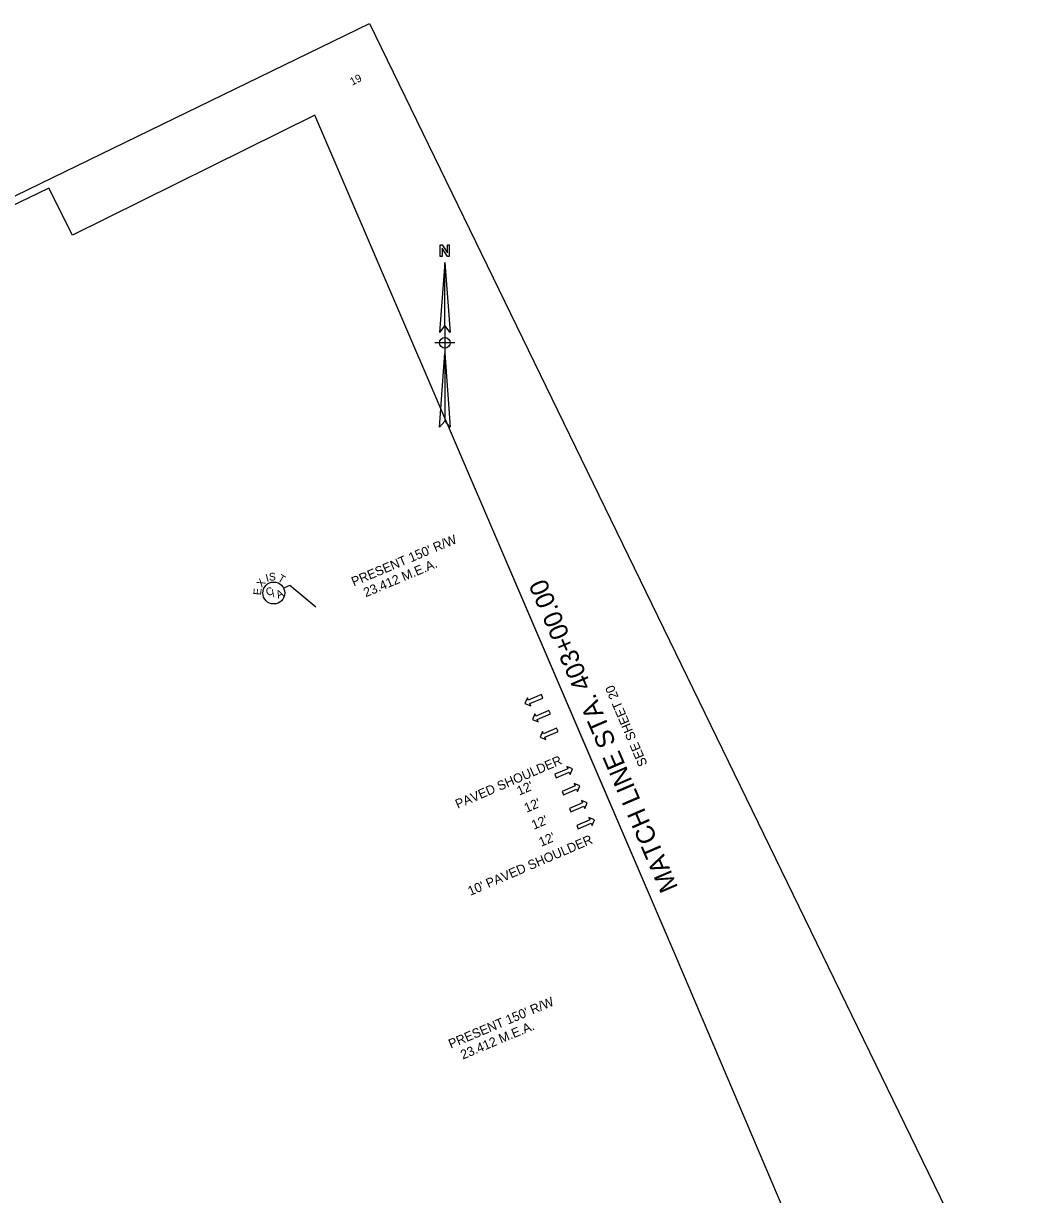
# Model space of a CAD drawing. Extents: x 1616869 to 1620470, y 1100482 to 1103335.
# Drawn here: x 1618151 to 1618793, y 1101340 to 1102097 of the extents above; entities that cross this region are included whole.
import ezdxf

# ---------------------------------------------------------------- set-up
doc = ezdxf.new("R2010")
doc.units = 0
for name, color, linetype in [('Level 2', 7, 'Continuous'), ('Level 4', 7, 'Continuous'), ('RD_PD_DR_Pipe', 7, 'Continuous'), ('RD_SHT_MatchLine', 7, 'Continuous'), ('RD_SHT_Misc2', 7, 'Continuous'), ('RD_SHT_TX', 7, 'Continuous'), ('RD_TX_RoadID', 7, 'Continuous'), ('RD_TX_RW', 7, 'Continuous')]:
    doc.layers.add(name, color=color, linetype=linetype)

msp = doc.modelspace()

# ---------------------------------------------------------------- linework, layer by layer
at = {"layer": 'Level 2'}
msp.add_lwpolyline([(1616868.78, 1101364.63), (1618375.15, 1102097.07), (1618793.41, 1101236.86), (1617287.04, 1100504.42)], close=True, dxfattribs=at)
at = {"layer": 'Level 4'}
msp.add_lwpolyline([(1617080.14, 1101099.03), (1617256.2, 1100856.12), (1617395.1, 1100558.35), (1618700.82, 1101193.66), (1618573.12, 1101494.1), (1618454.8, 1101769.78), (1618339.83, 1102037.66), (1618182.95, 1101960.1), (1618167.86, 1101990.6), (1616961.35, 1101407.95), (1616972.59, 1101384.68), (1616914.03, 1101356.41)], close=True, dxfattribs=at)
msp.add_lwpolyline([(1617080.14, 1101099.03), (1617256.2, 1100856.12), (1617395.1, 1100558.35), (1618700.82, 1101193.66), (1618573.12, 1101494.1), (1618454.8, 1101769.78), (1618339.83, 1102037.66), (1618182.95, 1101960.1), (1618167.86, 1101990.6), (1616961.35, 1101407.95), (1616972.59, 1101384.68), (1616914.03, 1101356.41)], close=True, dxfattribs=at)
at = {"layer": 'RD_PD_DR_Pipe'}
for p, q in [((1618319.54, 1101731.95), (1618323.66, 1101733.95)), ((1618323.66, 1101733.95), (1618340.43, 1101719.93))]:
    msp.add_line(p, q, dxfattribs=at)
msp.add_circle((1618313.17, 1101728.85), 7.08, dxfattribs=at)
at = {"layer": 'RD_SHT_MatchLine'}
msp.add_lwpolyline([(1618573.12, 1101494.1), (1618513.96, 1101631.94), (1618454.8, 1101769.78)], dxfattribs=at)
at = {"layer": 'RD_SHT_Misc2'}
for points in [[(1618487.13, 1101660.94), (1618486.19, 1101663.15), (1618477.74, 1101659.59), (1618477.11, 1101661.09), (1618475.6, 1101657.39), (1618479.31, 1101655.88), (1618478.67, 1101657.38)], [(1618491.98, 1101650.65), (1618491.05, 1101652.86), (1618482.6, 1101649.3), (1618481.97, 1101650.8), (1618480.46, 1101647.09), (1618484.16, 1101645.59), (1618483.53, 1101647.09)], [(1618496.94, 1101639.21), (1618496.01, 1101641.42), (1618487.56, 1101637.86), (1618486.92, 1101639.36), (1618485.41, 1101635.66), (1618489.12, 1101634.15), (1618488.49, 1101635.65)], [(1618494.85, 1101611.63), (1618495.8, 1101609.43), (1618504.23, 1101613.05), (1618504.87, 1101611.55), (1618506.35, 1101615.27), (1618502.64, 1101616.75), (1618503.28, 1101615.25)], [(1618499.59, 1101600.61), (1618500.53, 1101598.4), (1618508.96, 1101602.02), (1618509.61, 1101600.52), (1618511.09, 1101604.24), (1618507.37, 1101605.72), (1618508.02, 1101604.23)], [(1618504.32, 1101589.58), (1618505.27, 1101587.38), (1618513.7, 1101590.99), (1618514.34, 1101589.5), (1618515.82, 1101593.21), (1618512.11, 1101594.7), (1618512.75, 1101593.2)], [(1618509.06, 1101578.55), (1618510, 1101576.35), (1618518.43, 1101579.97), (1618519.07, 1101578.47), (1618520.56, 1101582.19), (1618516.84, 1101583.67), (1618517.48, 1101582.17)]]:
    msp.add_lwpolyline(points, close=True, dxfattribs=at)
at = {"layer": 'RD_SHT_TX'}
msp.add_line((1618496.66, 1101624.14), (1618496.66, 1101624.14), dxfattribs=at)
at = {"layer": 'RD_TX_RoadID'}
for p, q in [((1618423.74, 1101942.49), (1618420.32, 1101897.17)), ((1618423.74, 1101901.82), (1618420.32, 1101897.17)), ((1618423.74, 1101901.82), (1618423.74, 1101883.98)), ((1618430.26, 1101890.6), (1618417.28, 1101890.6)), ((1618423.74, 1101883.98), (1618427.15, 1101836.14)), ((1618427.15, 1101836.14), (1618423.74, 1101839.97))]:
    msp.add_line(p, q, dxfattribs=at)
msp.add_lwpolyline([(1618426.67, 1101946.31), (1618425.44, 1101946.31), (1618422.03, 1101951.78), (1618422.03, 1101950.96), (1618422.03, 1101946.31), (1618420.8, 1101946.31), (1618420.8, 1101953.9), (1618422.03, 1101953.9), (1618425.44, 1101948.84), (1618425.44, 1101949.25), (1618425.44, 1101953.9), (1618426.67, 1101953.9), (1618426.67, 1101946.31)], dxfattribs=at)
for points in [[(1618423.74, 1101942.49), (1618427.15, 1101897.17), (1618423.74, 1101901.82)], [(1618423.74, 1101883.98), (1618423.74, 1101839.97), (1618420.32, 1101836.14)]]:
    msp.add_lwpolyline(points, close=True, dxfattribs=at)
msp.add_circle((1618423.77, 1101890.6), 3.45, dxfattribs=at)

# ---------------------------------------------------------------- texts
at = {"layer": 'RD_PD_DR_Pipe'}
for s, rotation, p in [('X', 51.02398, (1618305.4, 1101732.09)), ('I', 15.86251, (1618308.69, 1101735.98)), ('S', 4.14202, (1618310.23, 1101736.74)), ('T', 328.98055, (1618315.31, 1101736.99)), ('E', 84.5111, (1618304.9, 1101727.27)), ('C', 25.92721, (1618309.43, 1101726.59)), ('/', 25.92721, (1618313.01, 1101725.99)), ('A', 25.92721, (1618316.05, 1101725.08))]:
    msp.add_text(s, height=5, rotation=rotation, dxfattribs=at).set_placement(p)
at = {"layer": 'RD_SHT_MatchLine'}
for s, height, p in [('MATCH LINE STA. 403+00.00', 12, (1618574.75, 1101538.46)), ('SEE SHEET 20', 6, (1618554.89, 1101618.23))]:
    msp.add_text(s, height=height, rotation=113.22835, dxfattribs=at).set_placement(p)
at = {"layer": 'RD_SHT_TX'}
for s, height, rotation, p in [('19', 5, 25.93046, (1618363.88, 1102056.84)), (' PAVED SHOULDER', 6, 23.23628, (1618430.05, 1101588.42)), ("12'", 6, 23.23465, (1618471.88, 1101597.81)), ("12'", 6, 23.23465, (1618476.61, 1101586.78)), ("12'", 6, 23.23465, (1618481.35, 1101575.76)), ("10' PAVED SHOULDER", 6, 23.23628, (1618440.24, 1101533.05)), ("12'", 6, 23.23465, (1618486.08, 1101564.73))]:
    msp.add_text(s, height=height, rotation=rotation, dxfattribs=at).set_placement(p)
at = {"layer": 'RD_TX_RW'}
for s, p in [("PRESENT 150' R/W ", (1618364.89, 1101733.08)), ('  23.412 M.E.A.', (1618368.57, 1101724.32)), ("PRESENT 150' R/W ", (1618427.65, 1101434.24)), ('  23.412 M.E.A.', (1618431.33, 1101425.48))]:
    msp.add_text(s, height=6, rotation=22.77639, dxfattribs=at).set_placement(p)

doc.saveas('drawing.dxf')
